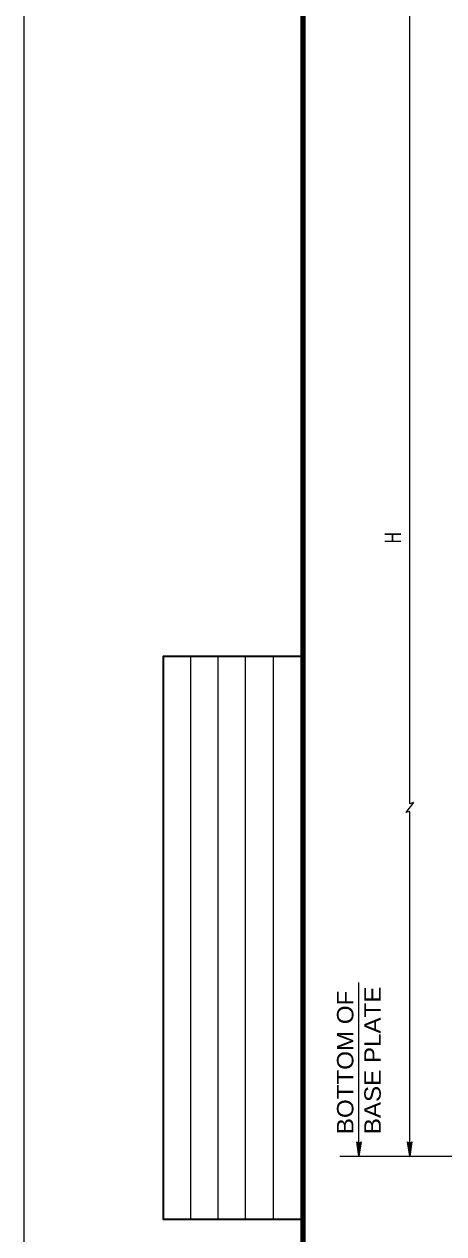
# Model space of a CAD drawing. Extents: x 312601.858 to 312602.699, y 144420.109 to 144420.704.
# Drawn here: x 312601.8578 to 312601.9345, y 144420.3449 to 144420.566 of the extents above; entities that cross this region are included whole.
import ezdxf

# ---------------------------------------------------------------- set-up
doc = ezdxf.new("R2010")
doc.units = 0
doc.header["$LTSCALE"] = 0.0012
for name, color, linetype, lineweight in [('1', 7, 'Continuous', 25), ('2', 7, 'Continuous', 13), ('39', 7, 'Continuous', 13), ('60', 7, 'Continuous', 25)]:
    doc.layers.add(name, color=color, linetype=linetype, lineweight=lineweight)

msp = doc.modelspace()

# ---------------------------------------------------------------- hatches: boundary and pattern name
at = {"layer": '39'}
for points in [[(312601.919, 144420.3614), (312601.9194, 144420.3617), (312601.919, 144420.3591), (312601.9186, 144420.3617)], [(312601.9283, 144420.3614), (312601.9287, 144420.3617), (312601.9283, 144420.3591), (312601.9279, 144420.3617)]]:
    msp.add_hatch(color=256, dxfattribs=at).paths.add_polyline_path(points)

# ---------------------------------------------------------------- linework, layer by layer
at = {"layer": '1', "lineweight": 13}
for p, q in [((312601.9283, 144420.4235), (312601.9283, 144420.5835)), ((312601.929, 144420.4237), (312601.9276, 144420.4219)), ((312601.929, 144420.4237), (312601.9283, 144420.4235)), ((312601.9283, 144420.4221), (312601.9276, 144420.4219)), ((312601.919, 144420.3591), (312601.919, 144420.3908)), ((312601.9155, 144420.3591), (312601.9447, 144420.3591))]:
    msp.add_line(p, q, dxfattribs=at)
msp.add_lwpolyline([(312601.9283, 144420.3591), (312601.9283, 144420.4106), (312601.9283, 144420.4221)], dxfattribs=at)
at = {"layer": '39', "lineweight": 25}
msp.add_line((312601.8578, 144420.1095), (312601.8578, 144420.7035), dxfattribs=at)
at = {"layer": '39', "lineweight": 158}
msp.add_line((312601.9088, 144420.1247), (312601.9088, 144420.6645), dxfattribs=at)
at = {"layer": '39'}
for points in [[(312601.919, 144420.3614), (312601.9194, 144420.3617), (312601.919, 144420.3591), (312601.9186, 144420.3617)], [(312601.9283, 144420.3614), (312601.9287, 144420.3617), (312601.9283, 144420.3591), (312601.9279, 144420.3617)]]:
    msp.add_lwpolyline(points, close=True, dxfattribs=at)
at = {"layer": '60'}
for p, q in [((312601.8883, 144420.3475), (312601.8883, 144420.4505)), ((312601.8933, 144420.3475), (312601.8933, 144420.4505)), ((312601.8983, 144420.3475), (312601.8983, 144420.4505)), ((312601.9034, 144420.3475), (312601.9034, 144420.4505))]:
    msp.add_line(p, q, dxfattribs=at)
at = {"layer": '60', "lineweight": 35}
msp.add_lwpolyline([(312601.9084, 144420.3475), (312601.8833, 144420.3475), (312601.8833, 144420.4505), (312601.9084, 144420.4505)], dxfattribs=at)

# ---------------------------------------------------------------- texts
at = {"layer": '2'}
for s, width, p in [('H', 0.7, (312601.9267, 144420.4711)), ('BOTTOM OF', 1.1, (312601.918, 144420.3631)), ('BASE PLATE', 1.1, (312601.923, 144420.3631))]:
    msp.add_text(s, height=0.003, rotation=90, dxfattribs=dict(at, width=width)).set_placement(p)

doc.saveas('drawing.dxf')
